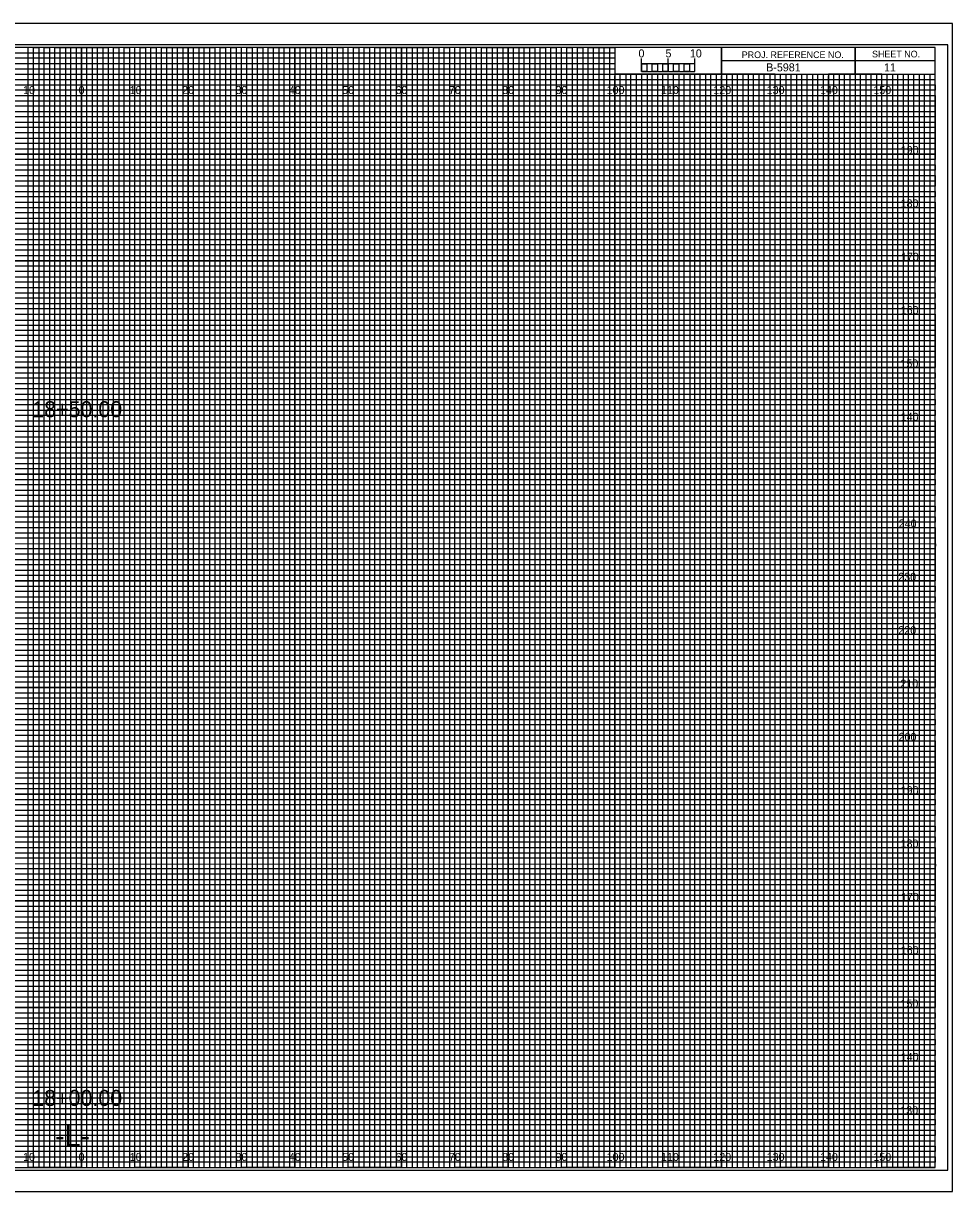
# Model space of a CAD drawing. Extents: x -13 to 323, y -5 to 4174.
# Drawn here: x 149.1 to 323.3, y 1095.5 to 1314.5 of the extents above; entities that cross this region are included whole.
import ezdxf

# ---------------------------------------------------------------- set-up
doc = ezdxf.new("R2010")
doc.units = 0
for name, color, linetype in [('Exist Cross Section Cell', 7, 'Continuous'), ('Exist XS Center Line Elevation Label', 7, 'Continuous'), ('Exist XS Ground Line', 7, 'Continuous'), ('Prop CMT Concrete Structures', 7, 'Continuous'), ('Prop CMT Guardrail Graphics', 7, 'Continuous'), ('Prop CMT Pvmt Course 1', 7, 'Continuous'), ('Prop CMT Pvmt Course 2', 7, 'Continuous'), ('Prop CMT Pvmt Course 3', 7, 'Continuous'), ('Prop CMT Pvmt Surface', 7, 'Continuous'), ('Prop CMT Shld Paved Course 1', 7, 'Continuous'), ('Prop CMT Shld Paved Course 2', 7, 'Continuous'), ('Prop CMT Shld Paved Course 3', 7, 'Continuous'), ('Prop CMT Subgrade Earthwork', 7, 'Continuous'), ('Prop XS Ditch Standard Text', 7, 'Continuous'), ('Prop XS SE Text', 7, 'Continuous'), ('Prop XS Side Slope Text', 7, 'Continuous'), ('Scratch_Level_0', 7, 'Continuous')]:
    doc.layers.add(name, color=color, linetype=linetype)

msp = doc.modelspace()

# ---------------------------------------------------------------- linework, layer by layer
at = {"layer": 'Exist XS Center Line Elevation Label'}
for points in [[(145, 1100), (155, 1100), (155, 1310), (165, 1310), (165, 1100), (175, 1100), (175, 1310), (185, 1310), (185, 1100), (195, 1100), (195, 1310), (205, 1310), (205, 1100), (215, 1100), (215, 1310), (225, 1310), (225, 1100), (235, 1100), (235, 1310), (245, 1310), (245, 1100), (255, 1100), (255, 1310), (259.93, 1310), (260, 1310), (260, 1305), (264.99, 1305), (264.99, 1100), (275, 1100), (275, 1305), (285, 1305), (285, 1100), (295, 1100), (295, 1305), (305, 1305), (305, 1100), (315, 1100), (315, 1305)], [(0, 1305), (275, 1305)], [(0, 1285), (320, 1285), (320, 1295), (0, 1295)], [(0, 1265), (320, 1265), (320, 1275), (0, 1275)], [(0, 1245), (320, 1245), (320, 1255), (0, 1255)], [(0, 1225), (320, 1225), (320, 1235), (0, 1235)], [(0, 1205), (320, 1205), (320, 1215), (0, 1215)], [(0, 1185), (320, 1185), (320, 1195), (0, 1195)], [(0, 1165), (320, 1165), (320, 1175), (0, 1175)], [(0, 1145), (320, 1145), (320, 1155), (0, 1155)], [(0, 1125), (320, 1125), (320, 1135), (0, 1135)], [(0, 1105), (320, 1105), (320, 1115), (0, 1115)]]:
    msp.add_lwpolyline(points, dxfattribs=at)
at = {"layer": 'Exist XS Ground Line'}
for p, q in [((150, 1310), (140, 1310)), ((150, 1100), (150, 1310)), ((170, 1310), (160, 1310)), ((160, 1310), (160, 1100)), ((170, 1100), (170, 1310)), ((190, 1310), (180, 1310)), ((180, 1310), (180, 1100)), ((190, 1100), (190, 1310)), ((210, 1310), (200, 1310)), ((200, 1310), (200, 1100)), ((210, 1100), (210, 1310)), ((230, 1310), (220, 1310)), ((220, 1310), (220, 1100)), ((230, 1100), (230, 1310)), ((250, 1310), (240, 1310)), ((240, 1310), (240, 1100)), ((250, 1100), (250, 1310)), ((260, 1310), (260, 1100)), ((270, 1100), (270, 1305)), ((290, 1305), (280, 1305)), ((280, 1305), (280, 1100)), ((290, 1100), (290, 1305)), ((310, 1305), (300, 1305)), ((300, 1305), (300, 1100)), ((310, 1100), (310, 1305)), ((160, 1100), (150, 1100)), ((180, 1100), (170, 1100)), ((200, 1100), (190, 1100)), ((220, 1100), (210, 1100)), ((240, 1100), (230, 1100)), ((260, 1100), (250, 1100)), ((280, 1100), (270, 1100)), ((300, 1100), (290, 1100)), ((320, 1100), (310, 1100)), ((320, 1100), (320, 1100))]:
    msp.add_line(p, q, dxfattribs=at)
for points in [[(0, 1300), (320, 1300), (320, 1290), (0, 1290)], [(0, 1280), (320, 1280), (320, 1270), (0, 1270)], [(0, 1260), (320, 1260), (320, 1250), (0, 1250)], [(0, 1240), (320, 1240), (320, 1230), (0, 1230)], [(0, 1220), (320, 1220), (320, 1210), (0, 1210)], [(0, 1200), (320, 1200), (320, 1190), (0, 1190)], [(0, 1180), (320, 1180), (320, 1170), (0, 1170)], [(0, 1160), (320, 1160), (320, 1150), (0, 1150)], [(0, 1140), (320, 1140), (320, 1130), (0, 1130)], [(0, 1120), (320, 1120), (320, 1110), (0, 1110)]]:
    msp.add_lwpolyline(points, dxfattribs=at)
at = {"layer": 'Prop CMT Pvmt Course 1'}
for p, q in [((323.3, 1314.5), (-13.4, 1314.5)), ((-13.4, 1095.5), (323.3, 1095.5))]:
    msp.add_line(p, q, dxfattribs=at)
at = {"layer": 'Prop CMT Pvmt Course 2'}
msp.add_lwpolyline([(-13.4, 1095.5), (323.3, 1095.5), (323.3, 1314.5), (-13.4, 1314.5)], close=True, dxfattribs=at)
at = {"layer": 'Prop CMT Pvmt Course 3'}
msp.add_lwpolyline([(-10.8, 1099.5), (322.4, 1099.5), (322.4, 1310.5), (-10.8, 1310.5)], close=True, dxfattribs=at)
at = {"layer": 'Prop CMT Shld Paved Course 1'}
for p, q in [((305, 1310), (305, 1305)), ((305, 1305), (305, 1310)), ((280, 1307.5), (280, 1305)), ((320, 1307.49), (280, 1307.49)), ((280, 1305), (320, 1305))]:
    msp.add_line(p, q, dxfattribs=at)
for points in [[(320, 1310), (0, 1310), (0, 1100), (320, 1100)], [(280, 1310), (260, 1310), (260, 1305.03), (280, 1305.03)], [(320, 1310), (280, 1310), (280, 1305), (320, 1305)]]:
    msp.add_lwpolyline(points, close=True, dxfattribs=at)
at = {"layer": 'Prop CMT Shld Paved Course 2'}
for p, q in [((267, 1305), (266.01, 1305)), ((266.01, 1305), (266.01, 1100)), ((267, 1100), (267, 1305)), ((269, 1305), (268, 1305)), ((268, 1305), (268, 1100)), ((269, 1100), (269, 1305)), ((266.01, 1100), (265, 1100)), ((268, 1100), (267, 1100))]:
    msp.add_line(p, q, dxfattribs=at)
for points in [[(150, 1100), (151, 1100), (151, 1310), (152, 1310), (152, 1100)], [(152, 1100), (153, 1100), (153, 1310), (154, 1310), (154, 1100)], [(155, 1100), (156, 1100), (156, 1310), (157, 1310), (157, 1100)], [(157, 1100), (158, 1100), (158, 1310), (159, 1310), (159, 1100)], [(160, 1100), (161, 1100), (161, 1310), (162, 1310), (162, 1100)], [(162, 1100), (163, 1100), (163, 1310), (164, 1310), (164, 1100)], [(165, 1100), (166, 1100), (166, 1310), (167, 1310), (167, 1100)], [(167, 1100), (168, 1100), (168, 1310), (169, 1310), (169, 1100)], [(170, 1100), (171, 1100), (171, 1310), (172, 1310), (172, 1100)], [(172, 1100), (173, 1100), (173, 1310), (174, 1310), (174, 1100)], [(175, 1100), (176, 1100), (176, 1310), (177, 1310), (177, 1100)], [(177, 1100), (178, 1100), (178, 1310), (179, 1310), (179, 1100)], [(180, 1100), (181, 1100), (181, 1310), (182, 1310), (182, 1100)], [(182, 1100), (183, 1100), (183, 1310), (184, 1310), (184, 1100)], [(185, 1100), (186, 1100), (186, 1310), (187, 1310), (187, 1100)], [(187, 1100), (188, 1100), (188, 1310), (189, 1310), (189, 1100)], [(190, 1100), (191, 1100), (191, 1310), (192, 1310), (192, 1100)], [(192, 1100), (193, 1100), (193, 1310), (194, 1310), (194, 1100)], [(195, 1100), (196, 1100), (196, 1310), (197, 1310), (197, 1100)], [(197, 1100), (198, 1100), (198, 1310), (199, 1310), (199, 1100)], [(200, 1100), (201, 1100), (201, 1310), (202, 1310), (202, 1100)], [(202, 1100), (203, 1100), (203, 1310), (204, 1310), (204, 1100)], [(205, 1100), (206, 1100), (206, 1310), (207, 1310), (207, 1100)], [(207, 1100), (208, 1100), (208, 1310), (209, 1310), (209, 1100)], [(210, 1100), (211, 1100), (211, 1310), (212, 1310), (212, 1100)], [(212, 1100), (213, 1100), (213, 1310), (214, 1310), (214, 1100)], [(215, 1100), (216, 1100), (216, 1310), (217, 1310), (217, 1100)], [(217, 1100), (218, 1100), (218, 1310), (219, 1310), (219, 1100)], [(220, 1100), (221, 1100), (221, 1310), (222, 1310), (222, 1100)], [(222, 1100), (223, 1100), (223, 1310), (224, 1310), (224, 1100)], [(225, 1100), (226, 1100), (226, 1310), (227, 1310), (227, 1100)], [(227, 1100), (228, 1100), (228, 1310), (229, 1310), (229, 1100)], [(230, 1100), (231, 1100), (231, 1310), (232, 1310), (232, 1100)], [(232, 1100), (233, 1100), (233, 1310), (234, 1310), (234, 1100)], [(235, 1100), (236, 1100), (236, 1310), (237, 1310), (237, 1100)], [(237, 1100), (238, 1100), (238, 1310), (239, 1310), (239, 1100)], [(240, 1100), (241, 1100), (241, 1310), (242, 1310), (242, 1100)], [(242, 1100), (243, 1100), (243, 1310), (244, 1310), (244, 1100)], [(245, 1100), (246, 1100), (246, 1310), (247, 1310), (247, 1100)], [(247, 1100), (248, 1100), (248, 1310), (249, 1310), (249, 1100)], [(250, 1100), (251, 1100), (251, 1310), (252, 1310), (252, 1100)], [(252, 1100), (253, 1100), (253, 1310), (254, 1310), (254, 1100)], [(255, 1100), (256, 1100), (256, 1310), (257, 1310), (257, 1100)], [(257, 1100), (258, 1100), (258, 1310), (259, 1310), (259, 1100)], [(260, 1100), (261, 1100), (261, 1305), (262.02, 1305), (262.02, 1100)], [(262, 1100), (263, 1100), (263, 1305), (263.99, 1305), (263.99, 1100)], [(270, 1100), (270.98, 1100), (270.98, 1305), (272, 1305), (272, 1100)], [(272, 1100), (273, 1100), (273, 1305), (274.05, 1305), (274.05, 1100)], [(275, 1100), (276, 1100), (276, 1305), (277, 1305), (277, 1100)], [(277, 1100), (278, 1100), (278, 1305), (279, 1305), (279, 1100)], [(280, 1100), (281, 1100), (281, 1305), (282, 1305), (282, 1100)], [(282, 1100), (283, 1100), (283, 1305), (284, 1305), (284, 1100)], [(285, 1100), (286, 1100), (286, 1305), (287, 1305), (287, 1100)], [(287, 1100), (288, 1100), (288, 1305), (289, 1305), (289, 1100)], [(290, 1100), (291, 1100), (291, 1305), (292, 1305), (292, 1100)], [(292, 1100), (293, 1100), (293, 1305), (294, 1305), (294, 1100)], [(295, 1100), (296, 1100), (296, 1305), (297, 1305), (297, 1100)], [(297, 1100), (298, 1100), (298, 1305), (299, 1305), (299, 1100)], [(300, 1100), (301, 1100), (301, 1305), (302, 1305), (302, 1100)], [(302, 1100), (303, 1100), (303, 1305), (304, 1305), (304, 1100)], [(305, 1100), (306, 1100), (306, 1305), (307, 1305), (307, 1100)], [(307, 1100), (308, 1100), (308, 1305), (309, 1305), (309, 1100)], [(310, 1100), (311, 1100), (311, 1305), (312, 1305), (312, 1100)], [(312, 1100), (313, 1100), (313, 1305), (314, 1305), (314, 1100)], [(315, 1100), (316, 1100), (316, 1305), (317, 1305), (317, 1100)], [(317, 1100), (318, 1100), (318, 1305), (319, 1305), (319, 1100)]]:
    msp.add_lwpolyline(points, dxfattribs=at)
at = {"layer": 'Prop CMT Shld Paved Course 3'}
for p, q in [((265, 1305.49), (265, 1307.9)), ((265, 1306.9), (265, 1307.9)), ((270, 1305.49), (270, 1307.9)), ((275, 1305.49), (275, 1307.9)), ((275, 1306.9), (275, 1307.9))]:
    msp.add_line(p, q, dxfattribs=at)
for points in [[(275, 1306.9), (265, 1306.9), (265, 1305.49), (275, 1305.49)], [(265, 1306.9), (266, 1306.9), (266, 1305.49), (265, 1305.49)], [(267, 1306.9), (268, 1306.9), (268, 1305.49), (267, 1305.49)], [(269, 1306.9), (270, 1306.9), (270, 1305.49), (269, 1305.49)], [(271, 1306.9), (272, 1306.9), (272, 1305.49), (271, 1305.49)], [(273, 1306.9), (274, 1306.9), (274, 1305.49), (273, 1305.49)]]:
    msp.add_lwpolyline(points, close=True, dxfattribs=at)
at = {"layer": 'Prop CMT Subgrade Earthwork'}
for p, q in [((150, 1100), (150, 1310)), ((160, 1100), (160, 1310)), ((170, 1100), (170, 1310)), ((180, 1100), (180, 1310)), ((190, 1100), (190, 1310)), ((200, 1100), (200, 1310)), ((210, 1100), (210, 1310)), ((220, 1100), (220, 1310)), ((230, 1100), (230, 1310)), ((240, 1100), (240, 1310)), ((250, 1100), (250, 1310)), ((260, 1100), (260, 1304.69)), ((270, 1100), (270, 1304.69)), ((280, 1100), (280, 1304.69)), ((290, 1100), (290, 1304.69)), ((300, 1100), (300, 1304.69)), ((310, 1100), (310, 1304.69)), ((0, 1300), (320, 1300)), ((0, 1290), (320, 1290)), ((0, 1280), (320, 1280)), ((0, 1270), (320, 1270)), ((0, 1260), (320, 1260)), ((0, 1250), (320, 1250)), ((0, 1240), (320, 1240)), ((0, 1230), (320, 1230)), ((0, 1220), (320, 1220)), ((0, 1210), (320, 1210)), ((0, 1200), (320, 1200)), ((0, 1190), (320, 1190)), ((0, 1180), (320, 1180)), ((0, 1170), (320, 1170)), ((0, 1160), (320, 1160)), ((0, 1150), (320, 1150)), ((0, 1140), (320, 1140)), ((0, 1130), (320, 1130)), ((0, 1120), (320, 1120)), ((0, 1110), (320, 1110))]:
    msp.add_line(p, q, dxfattribs=at)
at = {"layer": 'Scratch_Level_0'}
for p, q in [((0, 1309), (260, 1309)), ((260, 1307.98), (0, 1307.98)), ((260, 1309), (260, 1307.98)), ((0, 1307), (260, 1307)), ((260, 1305.89), (0, 1305.89)), ((260, 1307), (260, 1305.89)), ((0, 1304), (320, 1304))]:
    msp.add_line(p, q, dxfattribs=at)
for points in [[(0, 1303), (270, 1303), (320, 1303), (320, 1302), (0, 1302)], [(0, 1301), (320, 1301), (320, 1299), (0, 1299)], [(0, 1298), (320, 1298), (320, 1297), (0, 1296.98)], [(0, 1296), (320, 1296), (320, 1294), (0, 1294)], [(0, 1293), (320, 1293), (320, 1292), (0, 1292)], [(0, 1291), (320, 1291), (320, 1289), (0, 1289)], [(0, 1288), (320, 1288), (320, 1287), (0, 1287)], [(0, 1286), (320, 1286), (320, 1284), (0, 1284)], [(0, 1283), (320, 1283), (320, 1282), (0, 1282)], [(0, 1281), (320, 1281), (320, 1279), (0, 1279)], [(0, 1278), (320, 1278), (320, 1277), (0, 1277)], [(0, 1276), (320, 1276), (320, 1273.95), (320, 1273), (320, 1272), (0, 1272)], [(0, 1274), (320, 1274), (320, 1273), (0, 1273)], [(0, 1271), (320, 1271), (320, 1269), (0, 1269.03)], [(0, 1269.03), (320, 1269), (320, 1268), (0, 1268)], [(0, 1267), (320, 1267), (320, 1266), (0, 1266)], [(0, 1264), (320, 1264), (320, 1263), (0, 1263)], [(0, 1262), (320, 1262), (320, 1261), (0, 1261)], [(-0.07, 1258.89), (320, 1258.89), (320, 1257.88), (-0.07, 1257.88)], [(0, 1257), (320, 1257), (320, 1256), (0, 1256)], [(0, 1254), (320, 1254), (320, 1253), (0, 1253)], [(0, 1252), (320, 1252), (320, 1251), (0, 1251)], [(0, 1249), (320, 1249), (320, 1248), (0, 1248)], [(0, 1247), (320, 1247), (320, 1246), (0, 1246)], [(0, 1244), (320, 1244), (320, 1243), (0, 1243)], [(0, 1242), (320, 1242), (320, 1241), (0, 1241)], [(0, 1239), (320, 1239), (319.99, 1237.98), (0, 1238)], [(0, 1237), (320, 1237), (320, 1236), (0, 1236)], [(0, 1234), (320, 1234), (320, 1233), (0, 1233)], [(0, 1232), (320, 1232), (320, 1231), (0, 1231)], [(0, 1229), (320, 1229), (320, 1228), (0, 1228)], [(0, 1227), (320, 1227), (320, 1226), (0, 1226)], [(0, 1224), (320, 1224), (320, 1223), (0, 1223)], [(0, 1222), (320, 1222), (320, 1221), (0, 1221)], [(0, 1219), (320, 1219), (320, 1218), (0, 1218)], [(0, 1216.99), (320.07, 1216.91), (320, 1216), (0, 1216)], [(0, 1214), (320, 1214), (320, 1213), (0, 1213)], [(0, 1212), (320, 1212), (320, 1211), (0, 1211)], [(0, 1209), (320, 1209), (320, 1208), (0, 1208)], [(0, 1207), (320, 1207), (320, 1206), (0, 1206)], [(0, 1204), (320, 1204), (320, 1203), (0, 1203)], [(0, 1202), (320, 1202), (320, 1201), (0, 1201)], [(0, 1199), (320, 1199), (320, 1198), (0, 1198)], [(0, 1197), (320, 1197), (320, 1196), (0, 1196)], [(0, 1194), (320, 1194), (320, 1193), (0, 1193)], [(0, 1192), (320, 1192), (320, 1191), (0, 1191)], [(0, 1189), (320, 1189), (320, 1188), (0, 1188)], [(0, 1187), (320, 1187), (320, 1186), (0, 1186)], [(0, 1184), (320, 1184), (320, 1183), (0, 1183)], [(0, 1182), (320, 1182), (320, 1181), (0, 1181)], [(0, 1179), (320, 1179), (319.99, 1177.98), (0, 1178)], [(0, 1177), (320, 1177), (320, 1176), (0, 1176)], [(0, 1174), (320, 1174), (320, 1173), (0, 1173)], [(0, 1172), (320, 1172), (320, 1171), (0, 1171)], [(0, 1169), (320, 1169), (320, 1168), (0, 1168)], [(0, 1167), (320, 1167), (320, 1166), (0, 1166)], [(0, 1164), (320, 1164), (320, 1163), (0, 1163)], [(0, 1162), (320, 1162), (320, 1161), (0, 1161)], [(0, 1159), (320, 1159), (320, 1158), (0, 1158)], [(0, 1156.99), (320.07, 1156.91), (320, 1156), (0, 1156)], [(0, 1154), (320, 1154), (320, 1153), (0, 1153)], [(0, 1152), (320, 1152), (320, 1151), (0, 1151)], [(0, 1149), (320, 1149), (320, 1148), (0, 1148)], [(0, 1147), (320, 1147), (320, 1146), (0, 1146)], [(0, 1144), (320, 1144), (320, 1143), (0, 1143)], [(0, 1142), (320, 1142), (320, 1141), (0, 1141)], [(0, 1139), (320, 1139), (320, 1138), (0, 1138)], [(0, 1137), (320, 1137), (320, 1136), (0, 1136)], [(0, 1134), (320, 1134), (320, 1133), (0, 1133)], [(0, 1132), (320, 1132), (320, 1131), (0, 1131)], [(0, 1129), (320, 1129), (320, 1128), (0, 1128)], [(0, 1127), (320, 1127), (320, 1126), (0, 1126)], [(0, 1124), (320, 1124), (320, 1123), (0, 1123)], [(0, 1122), (320, 1122), (320, 1121), (0, 1121)], [(0, 1119), (320, 1119), (320, 1118), (0, 1118)], [(0, 1117), (320, 1117), (320, 1116), (0, 1116)], [(0, 1114), (320, 1114), (320, 1113), (0, 1113)], [(0, 1112), (320, 1112), (320, 1111), (0, 1111)], [(0, 1109), (320, 1109), (320, 1108), (0, 1108)], [(0, 1107), (320, 1107), (320, 1106), (0, 1106)], [(0, 1104), (320, 1104), (320, 1103), (0, 1103)], [(0, 1102), (320, 1102), (320, 1101), (0, 1101)]]:
    msp.add_lwpolyline(points, dxfattribs=at)

# ---------------------------------------------------------------- texts
at = {"layer": 'Exist Cross Section Cell'}
for s, p in [('10', (149.04, 1301.25)), ('0', (159.45, 1301.25)), ('0', (159.45, 1301.25)), ('10', (169.04, 1301.25)), ('20', (178.86, 1301.25)), ('30', (188.86, 1301.25)), ('40', (198.86, 1301.25)), ('50', (208.86, 1301.25)), ('60', (218.86, 1301.25)), ('70', (228.86, 1301.25)), ('80', (238.86, 1301.25)), ('90', (248.86, 1301.25)), ('100', (258.44, 1301.25)), ('110', (268.62, 1301.25)), ('120', (278.44, 1301.25)), ('130', (288.44, 1301.25)), ('140', (298.44, 1301.25)), ('150', (308.44, 1301.25)), ('10', (149.04, 1101.25)), ('0', (159.45, 1101.25)), ('0', (159.45, 1101.25)), ('10', (169.04, 1101.25)), ('20', (178.86, 1101.25)), ('30', (188.86, 1101.25)), ('40', (198.86, 1101.25)), ('50', (208.86, 1101.25)), ('60', (218.86, 1101.25)), ('70', (228.86, 1101.25)), ('80', (238.86, 1101.25)), ('90', (248.86, 1101.25)), ('100', (258.44, 1101.25)), ('110', (268.62, 1101.25)), ('120', (278.44, 1101.25)), ('130', (288.44, 1101.25)), ('140', (298.44, 1101.25)), ('150', (308.44, 1101.25))]:
    msp.add_text(s, height=1.5, dxfattribs=at).set_placement(p)
at = {"layer": 'Prop CMT Concrete Structures'}
for s, p in [('18+50.00', (150.77, 1240.67)), ('18+00.00', (150.77, 1111.56))]:
    msp.add_text(s, height=3, dxfattribs=at).set_placement(p)
at = {"layer": 'Prop CMT Guardrail Graphics'}
for s, p in [('190', (313.57, 1290)), ('180', (313.55, 1280)), ('170', (313.61, 1270)), ('160', (313.57, 1260)), ('150', (313.52, 1250)), ('140', (313.57, 1240)), ('240', (313.19, 1220)), ('230', (313.11, 1210)), ('220', (313.12, 1200)), ('210', (313.5, 1190)), ('200', (313.17, 1180)), ('190', (313.57, 1170)), ('180', (313.55, 1160)), ('170', (313.61, 1150)), ('160', (313.57, 1140)), ('150', (313.52, 1130)), ('140', (313.57, 1120)), ('130', (313.49, 1110))]:
    msp.add_text(s, height=1.5, dxfattribs=at).set_placement(p)
at = {"layer": 'Prop CMT Pvmt Surface'}
for s, p in [('5', (269.47, 1308.12)), ('10', (274.04, 1308.12))]:
    msp.add_text(s, height=1.5, dxfattribs=at).set_placement(p)
at = {"layer": 'Prop CMT Shld Paved Course 1'}
for s, p in [('PROJ. REFERENCE NO.', (283.77, 1307.99)), ('SHEET NO.', (308.19, 1308.12))]:
    msp.add_text(s, height=1.25, dxfattribs=at).set_placement(p)
at = {"layer": 'Prop CMT Shld Paved Course 3'}
msp.add_text('0', height=1.5, dxfattribs=at).set_placement((264.41, 1308.12))
at = {"layer": 'Prop XS Ditch Standard Text'}
msp.add_text('-L-', height=4, dxfattribs=at).set_placement((155.06, 1104))
at = {"layer": 'Prop XS SE Text'}
msp.add_text(' B-5981', height=1.5, dxfattribs=at).set_placement((287.79, 1305.5))
at = {"layer": 'Prop XS Side Slope Text'}
msp.add_text('11', height=1.5, dxfattribs=at).set_placement((310.44, 1305.5))

doc.saveas('drawing.dxf')
